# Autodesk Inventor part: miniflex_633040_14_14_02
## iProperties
Shininess: 64.0
Length Units: 11269
Angle Units: 11279
Time Units: 11290
Mass Units: 11283
Length Display Precision: 3
Angle Display Precision: 2
Compacted: True
Part Number: miniflex_633040_14_14_02
Document SubType Name: Modeling
Created: 2005-02
Material: Par défaut
Designer: LEGERET Philippe
Density: 0.0
Volumn: 0.0
Area: 0.0
PropertySet Name: Model Information
Control State: 0
Master: False
Checked Out: False
Author: LEGERET Philippe
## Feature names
1. Base1
